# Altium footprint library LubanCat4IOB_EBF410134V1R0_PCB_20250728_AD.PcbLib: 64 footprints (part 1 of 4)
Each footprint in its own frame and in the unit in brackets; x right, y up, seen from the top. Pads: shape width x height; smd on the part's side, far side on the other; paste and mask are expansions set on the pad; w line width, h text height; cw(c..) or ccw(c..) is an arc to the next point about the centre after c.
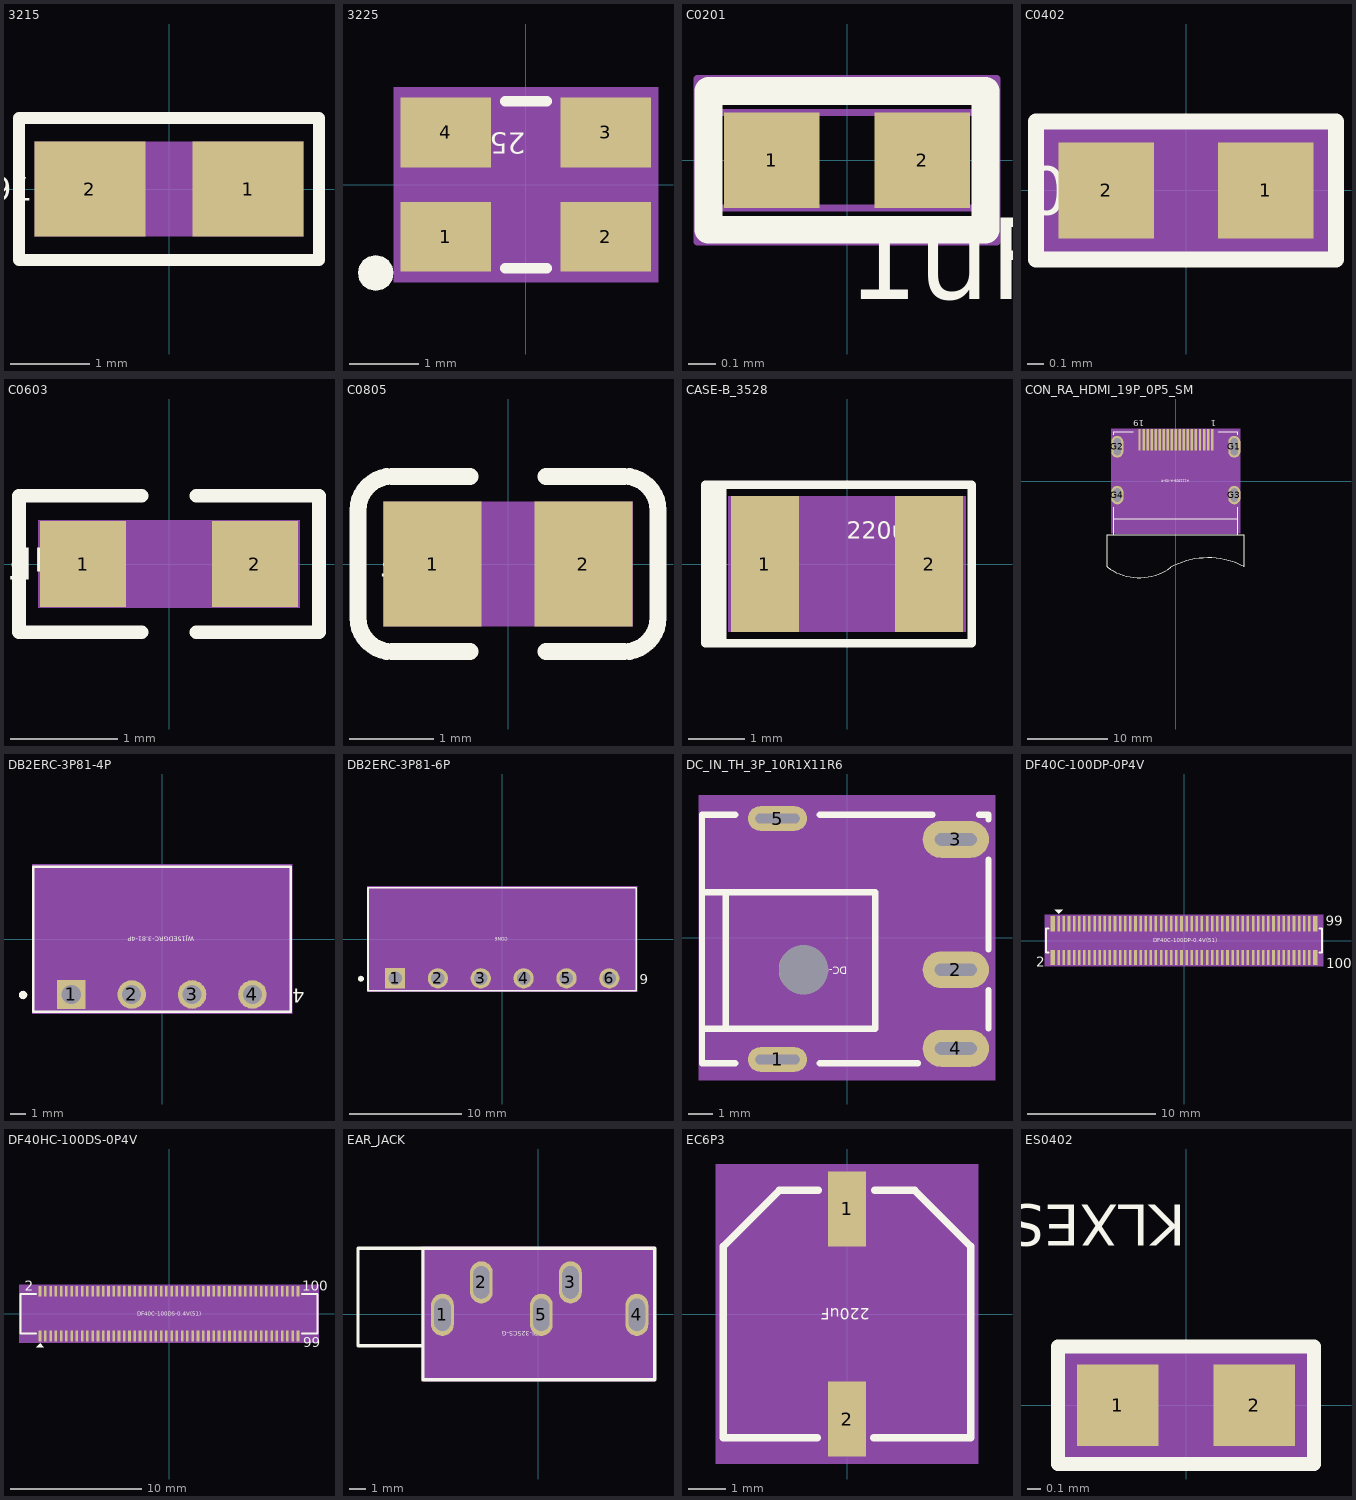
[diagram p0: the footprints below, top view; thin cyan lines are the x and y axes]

## 3215 [mm] "3215"
pads (2):
  rect 1.4x1.2 smd: 1(1.001,0) 2(-1.001,0)
Top Overlay:
  lines w0.15: -1.9,-0.899 1.9,-0.899 1.9,0.899 -1.9,0.899 -1.9,-0.899
  text "32.768KHz" at -1.08,0.15 h0.3
Top 3D Body:
  region: 1.699,0.599 1.699,-0.599 -1.699,-0.599 -1.699,0.599
Mechanical 17:
  text "1" at 0.848,0 h0.38
  text "2" at -1.153,0 h0.38
3D body: height 3.81, standoff 0, extent -1.699,-0.599 1.699,0.599

## 3225 [mm] "3225"
pads (4):
  rect 1.3x1 smd: 1(-1.15,-0.75) 2(1.15,-0.75) 3(1.15,0.75) 4(-1.15,0.75)
Top Overlay:
  dashed: -2.159,-1.525 -2.257,-1.505 -2.339,-1.45 -2.394,-1.368 -2.414,-1.27 -2.394,-1.172 -2.376,-1.145 -2.339,-1.09 -2.257,-1.035 -2.159,-1.015 -2.061,-1.035 -1.979,-1.09 -1.942,-1.145 -1.924,-1.172 -1.904,-1.27 -1.924,-1.368 -1.979,-1.45 -2.061,-1.505
  lines w0.15: -0.3,-1.2 0.3,-1.2 ; -0.3,1.2 0.3,1.2
  text "25MHz" at 0,0.75 h0.3
Top 3D Body:
  region: -1.9,1.4 -1.9,-1.4 1.9,-1.4 1.9,1.4
Mechanical 17:
  text "1" at -1.15,-0.384 h0.91
  text "3" at 1.15,1.116 h0.91
  text "4" at -1.15,1.116 h0.91
  text "2" at 1.15,-0.384 h0.91
Top Assembly:
  lines w0.15: -1.6,-1.25 1.6,-1.25 1.6,1.25 -1.6,1.25 -1.6,-1.25
3D body: height 3.81, standoff 0, extent -1.9,-1.4 1.9,1.4

## C0201 [mm] "C0201"
pads (2):
  rect 0.35x0.35 smd: 1(-0.275,0) 2(0.275,0)
Top Overlay:
  lines w0.102: -0.508,-0.254 0.508,-0.254 0.508,0.254 -0.508,0.254 -0.508,-0.254
  text ".Designator" at 0.762,-1.422 h0.76
  text "1uF" at 0,-0.51 h0.3
Top 3D Body:
  lines w0.025: -0.475,-0.175 -0.475,0.175 0.475,0.175 0.475,-0.175 -0.475,-0.175
Mechanical 17:
  text "1" at -0.275,-0.305 h0.76
  text "2" at 0.275,-0.305 h0.76
Top Assembly:
  lines w0.025: -0.55,-0.3 -0.55,0.3 0.55,0.3 0.55,-0.3 -0.55,-0.3 ; -0.475,-0.175 -0.475,0.175 0.475,0.175 0.475,-0.175 -0.475,-0.175
  text "1uF" at 0.762,-0.254 h0.76

## C0402 [mm] "C0402"
pads (2):
  rect 0.599x0.599 smd: 1(0.5,0) 2(-0.5,0)
Top Overlay:
  lines w0.102: -0.94,-0.432 0.94,-0.432 0.94,0.432 -0.94,0.432 -0.94,-0.432
  text "10uF" at -0.48,0.15 h0.3
Top 3D Body:
  region: -0.94,-0.432 -0.94,0.432 0.94,0.432 0.94,-0.432
Mechanical 17:
  text "1" at 0.246,0 h0.64
  text "2" at -0.754,0 h0.64
Top Assembly:
  dashed: 0.94,0.432 0.94,-0.432 -0.94,-0.432 -0.94,0.432
3D body: height 3.81, standoff 0, extent -0.94,-0.432 0.94,0.432

## C0603 [mil] "C0603"
pads (2):
  rect 31.5x31.5 smd: 1(-31.5,0) 2(31.5,0)
Top Overlay:
  lines w5: -10,-25 -55,-25 -55,25 -10,25 ; 10,-25 55,-25 55,25 10,25
  text "22uF" at -18.9,5.91 h11.81
Top 3D Body:
  region: -48,16 48,16 48,-16 -48,-16
Mechanical 17:
  text "2" at 13.5,0 h45
  text "1" at -49.5,0 h45
Top Assembly:
  text "C0603" at -117,37 h30
3D body: height 150, standoff 0, extent -48,-16 48,16

## C0805 [mm] "C0805"
pads (2):
  rect 1.16x1.47 smd: 1(-0.89,0) 2(0.89,0)
Top Overlay:
  lines w0.2: -0.45,-1.035 -1.37,-1.035 cw(c-1.37,-0.635) -1.77,-0.635 -1.77,0.635 cw(c-1.37,0.635) -1.37,1.035 -0.45,1.035 ; 0.45,-1.035 1.37,-1.035 ccw(c1.37,-0.635) 1.77,-0.635 1.77,0.635 ccw(c1.37,0.635) 1.37,1.035 0.45,1.035
  text "47uF" at -0.48,0.15 h0.3
Top 3D Body:
  region: -1.47,-0.735 -1.47,0.735 1.47,0.735 1.47,-0.735
Mechanical 17:
  text "2" at 0.575,0 h0.79
  text "1" at -1.205,0 h0.79
3D body: height 3.81, standoff 0, extent -1.47,-0.735 1.47,0.735

## CASE-B_3528 [mm] "CASE-B_3528"
pads (2):
  rect 1.2x2.4 smd: 1(-1.45,0) 2(1.45,0)
Top Overlay:
  lines w0.15: -2.2,1.4 -2.2,-1.4 ; -2.1,-1.4 -2.3,-1.4 -2.3,1.4 ; -2.4,-1.4 -2.4,1.4 ; -2.4,-1.4 -2.2,-1.4 ; -2.4,-1.4 -2.5,-1.4 -2.5,1.4 -2.4,1.4 ; -2.4,1.4 -2.3,1.4 ; -2.3,1.4 2.2,1.4 2.2,-1.4 -2.2,-1.4
  text "220uF" at 0,0.45 h0.3
Top 3D Body:
  region: -2.1,1.2 -2.1,-1.2 2.1,-1.2 2.1,1.2
Mechanical 17:
  text "1" at -1.45,0.254 h0.64
  text "2" at 1.45,0.254 h0.64
Top Assembly:
  lines w0.15: -1.72,-1.1 1.78,-1.1 1.78,1.1 -1.72,1.1 -1.72,-1.1
3D body: height 3.81, standoff 0, extent -2.1,-1.2 2.1,1.2

## CON_RA_HDMI_19P_0P5_SM [mil] "CON_RA_HDMI_19P_0P5_SM"
pads (23):
  rect 12x106 smd: 1(177.17,201.35) 2(157.48,201.35) 3(137.8,201.35) 4(118.11,201.35) 5(98.43,201.35) 6(78.74,201.35) 7(59.06,201.35) 8(39.37,201.35) 9(19.69,201.35) 10(0,201.35) 11(-19.69,201.35) 12(-39.37,201.35) 13(-59.06,201.35) 14(-78.74,201.35) 15(-98.43,201.35) 16(-118.11,201.35) 17(-137.8,201.35) 18(-157.48,201.35) 19(-177.17,201.35)
  oval 59x106 / inner round 60 / far side oval 59x106 hole 83 slot 35 at 0 deg: G1(285.43,167.89) G2(-285.43,167.89)
  oval 59x90 / inner round 60 / far side oval 59x90 hole 66 slot 35 at 0 deg: G3(285.43,-68.33) G4(-285.43,-68.33)
Top Overlay:
  lines w5.91: -303.26,-261.35 -303.26,-182.61 303.26,-182.61 303.26,-261.35 ; -334.65,-418.83 ccw(c-178.55,-211.88) -23.62,-419.71 cw(c156.34,-755.43) 334.65,-418.83 334.65,-261.35 -334.65,-261.35 -334.65,-418.83
  lines w6: -303.26,-128.37 -303.26,-261.35 303.26,-261.35 303.26,-128.37 ; -303.26,225.96 -303.26,240.83 -206.69,240.83 ; 206.69,240.83 303.26,240.83 303.26,225.96
  text "19" at -154.21,297.54 h30
  text "1" at 197.79,297.54 h30
  text "A111926-A-05-R" at 66.14,5.91 h11.81
Top Courtyard:
  dashed: -314.93,-254.35 314.93,-254.35 314.93,254.35 -314.93,254.35
Bottom Courtyard:
  drawing of 4 lines, arcs and shapes, not listed
Top 3D Body:
  region: -314.93,-254.35 314.93,-254.35 314.93,254.35 -314.93,254.35
Top Component Center:
  lines w1: -10,-10.26 10,-10.26 ; 0,-20.26 0,-0.26
Mechanical 17:
  text "18" at -141.74,201.35 h9.84
  text "10" at 15.74,201.35 h9.84
  text "16" at -102.37,201.35 h9.84
  text "15" at -82.69,201.35 h9.84
  text "13" at -43.31,201.35 h9.84
  text "12" at -23.63,201.35 h9.84
  text "9" at 27.56,201.35 h9.84
  text "7" at 66.93,201.35 h9.84
  text "6" at 86.61,201.35 h9.84
  text "4" at 125.98,201.35 h9.84
  text "3" at 145.67,201.35 h9.84
  text "1" at 185.04,201.35 h9.84
  text "19" at -161.43,201.35 h9.84
  text "14" at -63,201.35 h9.84
  text "G3" at 301.17,-68.33 h9.84
  text "G1" at 301.17,167.89 h9.84
  text "G4" at -269.69,-68.33 h9.84
  text "G2" at -269.69,167.89 h9.84
  text "5" at 106.3,201.35 h9.84
  text "2" at 165.35,201.35 h9.84
  text "8" at 47.24,201.35 h9.84
  text "11" at -3.94,201.35 h9.84
  text "17" at -122.06,201.35 h9.84
Top Assembly:
  lines w6: -296.26,-254.35 296.26,-254.35 296.26,233.83 -296.26,233.83 -296.26,-254.35
  text "1" at 169.54,281.35 h25
  text "19" at -199.02,277.07 h25
3D body: height 150, standoff 0, extent -314.93,-254.35 314.93,254.35

## DB2ERC-3P81-4P [mm] "DB2ERC-3P81-4P"
pads (4):
  rect 1.8x1.8 / inner round 1.524 / far side rect 1.8x1.8 hole 1.2: 1(-5.725,-3.5)
  round 1.8 / inner round 1.524 / far side round 1.8 hole 1.2: 2(-1.915,-3.5) 3(1.895,-3.5) 4(5.705,-3.5)
Top Overlay:
  dashed: -9.021,-3.53 -9.002,-3.628 -8.946,-3.71 -8.864,-3.765 -8.766,-3.785 -8.669,-3.765 -8.641,-3.747 -8.586,-3.71 -8.531,-3.628 -8.511,-3.53 -8.531,-3.432 -8.586,-3.35 -8.641,-3.313 -8.669,-3.294 -8.766,-3.275 -8.864,-3.294 -8.946,-3.35 -9.002,-3.432
  lines w0.15: -8.13,-4.6 8.11,-4.6 8.11,4.55 -8.13,4.55 -8.13,-4.6
  text "WJ15EDGRC-3.81-4P" at 2.04,0.15 h0.3
  text "4" at 9.014,-3.149 h0.89
Top 3D Body:
  region: -8.2,4.7 -8.2,-4.7 8.2,-4.7 8.2,4.7
Mechanical 17:
  text "3" at 2.149,-3.5 h0.64
  text "1" at -5.471,-3.5 h0.64
  text "2" at -1.661,-3.5 h0.64
  text "4" at 5.959,-3.5 h0.64
3D body: height 3.81, standoff 0, extent -8.2,-4.7 8.2,4.7

## DB2ERC-3P81-6P [mm] "DB2ERC-3P81-6P"
pads (6):
  rect 1.8x1.8 / inner round 1.524 / far side rect 1.8x1.8 hole 1.2: 1(-9.525,-3.5)
  round 1.8 hole 1.2: 2(-5.715,-3.5) 5(5.715,-3.5)
  round 1.8 / inner round 1.524 / far side round 1.8 hole 1.2: 3(-1.905,-3.5) 4(1.905,-3.5) 6(9.525,-3.5)
Top Overlay:
  dashed: -12.818,-3.53 -12.799,-3.628 -12.743,-3.71 -12.661,-3.766 -12.563,-3.785 -12.466,-3.766 -12.438,-3.747 -12.383,-3.71 -12.328,-3.628 -12.308,-3.53 -12.328,-3.432 -12.383,-3.35 -12.438,-3.313 -12.466,-3.294 -12.563,-3.275 -12.661,-3.294 -12.743,-3.35 -12.799,-3.432
  lines w0.15: -11.93,-4.6 11.93,-4.6 11.93,4.55 -11.93,4.55 -11.93,-4.6
  text "CON6" at 0.48,0.15 h0.3
  text "6" at 12.964,-3.149 h0.89
Top 3D Body:
  region: -12,4.7 -12,-4.7 12,-4.7 12,4.7
Mechanical 17:
  text "3" at -1.651,-3.5 h0.64
  text "6" at 9.779,-3.5 h0.64
  text "1" at -9.271,-3.5 h0.64
  text "4" at 2.159,-3.5 h0.64
  text "5" at 5.969,-3.5 h0.64
  text "2" at -5.461,-3.5 h0.64
3D body: height 3.81, standoff 0, extent -12,-4.7 12,4.7

## DC_IN_TH_3P_10R1X11R6 [mm] "DC_IN_TH_3P_10R1X11R6"
pads (6):
  oval 2.4x1.001 hole 1.801 slot 0.399 at 90 deg: 1(-2.826,-4.951) 5(-2.826,4.849)
  oval 2.7x1.5 hole 1.7 slot 0.5 at 90 deg: 2(4.426,-1.301) 3(4.426,3.998)
  oval 2.7x1.5 / inner round 1.524 / far side oval 2.7x1.5 hole 1.7 slot 0.5 at 90 deg: 4(4.426,-4.501)
  round 1.999 hole 1.999 unplated: ""(-1.774,-1.301)
Top Overlay:
  lines w0.254: -5.899,-3.701 1.149,-3.701 1.149,1.849 -5.65,1.849 -5.899,1.849 ; -4.926,-3.701 -4.926,1.849 ; -4.545,-5.1 -5.899,-5.1 -5.899,4.999 -4.545,4.999 ; -1.104,-5.1 2.887,-5.1 ; -1.104,4.999 3.479,4.999 ; 5.371,4.999 5.749,4.999 5.749,4.818 ; 5.749,-3.683 5.749,-2.121 ; 5.749,-0.483 5.749,3.18
  text "DC-044A-20A" at 0,-1.17 h0.3
Top 3D Body:
  region: -6.026,-5.801 6.026,-5.801 6.026,5.801 -6.026,5.801
Mechanical 17:
  text "4" at 4.426,-4.755 h0.64
  text "1" at -2.826,-5.205 h0.64
  text "5" at -2.826,4.595 h0.64
  text "2" at 4.426,-1.555 h0.64
  text "3" at 4.426,3.744 h0.64
Mechanical 19:
  dashed: -5.899,-3.602 1.05,-3.602 1.05,1.75 -5.899,1.75 -5.899,1.999 1.299,1.999 1.299,-3.851 -5.899,-3.851
3D body: height 3.81, standoff 0, extent -6.026,-5.801 6.026,5.801

## DF40C-100DP-0P4V [mm] "DF40C-100DP-0P4V"
pads (104):
  rect 0.2x1.2 smd: 1(-9.8,1.325) 2(-9.8,-1.325) 3(-9.4,1.325) 4(-9.4,-1.325) 5(-9,1.325) 6(-9,-1.325) 7(-8.6,1.325) 8(-8.6,-1.325) 9(-8.2,1.325) 10(-8.2,-1.325) 11(-7.8,1.325) 12(-7.8,-1.325) 13(-7.4,1.325) 14(-7.4,-1.325) 15(-7,1.325) 16(-7,-1.325) 17(-6.6,1.325) 18(-6.6,-1.325) 19(-6.2,1.325) 20(-6.2,-1.325) 21(-5.8,1.325) 22(-5.8,-1.325) 23(-5.4,1.325) 24(-5.4,-1.325) 25(-5,1.325) 26(-5,-1.325) 27(-4.6,1.325) 28(-4.6,-1.325) 29(-4.2,1.325) 30(-4.2,-1.325) 31(-3.8,1.325) 32(-3.8,-1.325) 33(-3.4,1.325) 34(-3.4,-1.325) 35(-3,1.325) 36(-3,-1.325) 37(-2.6,1.325) 38(-2.6,-1.325) 39(-2.2,1.325) 40(-2.2,-1.325) 41(-1.8,1.325) 42(-1.8,-1.325) 43(-1.4,1.325) 44(-1.4,-1.325) 45(-1,1.325) 46(-1,-1.325) 47(-0.6,1.325) 48(-0.6,-1.325) 49(-0.2,1.325) 50(-0.2,-1.325) 51(0.2,1.325) 52(0.2,-1.325) 53(0.6,1.325) 54(0.6,-1.325) 55(1,1.325) 56(1,-1.325) 57(1.4,1.325) 58(1.4,-1.325) 59(1.8,1.325) 60(1.8,-1.325) 61(2.2,1.325) 62(2.2,-1.325) 63(2.6,1.325) 64(2.6,-1.325) 65(3,1.325) 66(3,-1.325) 67(3.4,1.325) 68(3.4,-1.325) 69(3.8,1.325) 70(3.8,-1.325) 71(4.2,1.325) 72(4.2,-1.325) 73(4.6,1.325) 74(4.6,-1.325) 75(5,1.325) 76(5,-1.325) 77(5.4,1.325) 78(5.4,-1.325) 79(5.8,1.325) 80(5.8,-1.325) 81(6.2,1.325) 82(6.2,-1.325) 83(6.6,1.325) 84(6.6,-1.325) 85(7,1.325) 86(7,-1.325) 87(7.4,1.325) 88(7.4,-1.325) 89(7.8,1.325) 90(7.8,-1.325) 91(8.2,1.325) 92(8.2,-1.325) 93(8.6,1.325) 94(8.6,-1.325) 95(9,1.325) 96(9,-1.325) 97(9.4,1.325) 98(9.4,-1.325) 99(9.8,1.325) 100(9.8,-1.325)
  rect 0.35x1.2 smd: 101(-10.275,1.325) 102(-10.275,-1.325) 103(10.275,1.325) 104(10.275,-1.325)
Top Overlay:
  dashed: -10.1,2.4 -9.5,2.4 -9.8,2.1
  lines w0.15: -10.6,-0.925 -10.8,-0.925 -10.8,0.925 -10.6,0.925 ; 10.6,-0.925 10.8,-0.925 10.8,0.925 10.6,0.925
  text "DF40C-100DP-0.4V(51)" at -2.4,-0.15 h0.3
  text "99" at 11.075,1.142 h0.76
  text "100" at 11.126,-2.16 h0.76
  text "2" at -11.582,-2.033 h0.76
Top 3D Body:
  region: -10.9,2 -10.9,-2 10.9,-2 10.9,2
Mechanical 17:
  text "13" at -7.523,1.342 h0.3
  text "15" at -7.123,1.342 h0.3
  text "20" at -6.34,-1.325 h0.3
  text "22" at -5.94,-1.325 h0.3
  text "24" at -5.54,-1.325 h0.3
  text "26" at -5.14,-1.325 h0.3
  text "29" at -4.322,1.342 h0.3
  text "3" at -9.403,1.342 h0.3
  text "30" at -4.34,-1.325 h0.3
  text "31" at -3.922,1.342 h0.3
  text "32" at -3.94,-1.325 h0.3
  text "35" at -3.122,1.342 h0.3
  text "36" at -3.14,-1.325 h0.3
  text "37" at -2.722,1.342 h0.3
  text "38" at -2.74,-1.325 h0.3
  text "39" at -2.322,1.342 h0.3
  text "40" at -2.34,-1.325 h0.3
  text "41" at -1.922,1.342 h0.3
  text "42" at -1.94,-1.325 h0.3
  text "43" at -1.522,1.342 h0.3
  text "45" at -1.122,1.342 h0.3
  text "47" at -0.722,1.342 h0.3
  text "49" at -0.322,1.342 h0.3
  text "5" at -9.003,1.342 h0.3
  text "53" at 0.477,1.342 h0.3
  text "55" at 0.877,1.342 h0.3
  text "7" at -8.603,1.342 h0.3
  text "9" at -8.203,1.342 h0.3
  text "72" at 4.06,-1.325 h0.3
  text "86" at 6.86,-1.325 h0.3
  text "84" at 6.46,-1.325 h0.3
  text "48" at -0.74,-1.325 h0.3
  text "50" at -0.34,-1.325 h0.3
  text "64" at 2.46,-1.325 h0.3
  text "71" at 4.077,1.342 h0.3
  text "60" at 1.66,-1.325 h0.3
  text "69" at 3.677,1.342 h0.3
  text "63" at 2.477,1.342 h0.3
  text "61" at 2.077,1.342 h0.3
  text "59" at 1.677,1.342 h0.3
  text "90" at 7.66,-1.325 h0.3
  text "88" at 7.26,-1.325 h0.3
  text "62" at 2.06,-1.325 h0.3
  text "66" at 2.86,-1.325 h0.3
  text "25" at -5.122,1.342 h0.3
  text "67" at 3.277,1.342 h0.3
  text "46" at -1.14,-1.325 h0.3
  text "65" at 2.877,1.342 h0.3
  text "70" at 3.66,-1.325 h0.3
  text "21" at -5.922,1.342 h0.3
  text "74" at 4.46,-1.325 h0.3
  text "68" at 3.26,-1.325 h0.3
  text "23" at -5.522,1.342 h0.3
  text "19" at -6.323,1.342 h0.3
  text "54" at 0.46,-1.325 h0.3
  text "56" at 0.86,-1.325 h0.3
  text "98" at 9.26,-1.325 h0.3
  text "96" at 8.86,-1.325 h0.3
  text "94" at 8.46,-1.325 h0.3
  text "92" at 8.06,-1.325 h0.3
  text "85" at 6.878,1.342 h0.3
  text "83" at 6.478,1.342 h0.3
  text "6" at -9.02,-1.325 h0.3
  text "4" at -9.42,-1.325 h0.3
  text "10" at -8.34,-1.325 h0.3
  text "8" at -8.62,-1.325 h0.3
  text "16" at -7.14,-1.325 h0.3
  text "14" at -7.54,-1.325 h0.3
  text "78" at 5.26,-1.325 h0.3
  text "80" at 5.66,-1.325 h0.3
  text "89" at 7.678,1.342 h0.3
  text "87" at 7.278,1.342 h0.3
  text "77" at 5.277,1.342 h0.3
  text "75" at 4.877,1.342 h0.3
  text "81" at 6.077,1.342 h0.3
  text "95" at 8.878,1.342 h0.3
  text "93" at 8.478,1.342 h0.3
  text "99" at 9.678,1.342 h0.3
  text "97" at 9.278,1.342 h0.3
  text "82" at 6.06,-1.325 h0.3
  text "100" at 9.54,-1.325 h0.3
  text "104" at 10.015,-1.325 h0.3
  text "1" at -9.803,1.342 h0.3
  text "2" at -9.82,-1.325 h0.3
  text "58" at 1.26,-1.325 h0.3
  text "79" at 5.677,1.342 h0.3
  text "52" at 0.06,-1.325 h0.3
  text "101" at -10.535,1.325 h0.3
  text "102" at -10.535,-1.325 h0.3
  text "11" at -7.923,1.342 h0.3
  text "17" at -6.723,1.342 h0.3
  text "12" at -7.94,-1.325 h0.3
  text "18" at -6.74,-1.325 h0.3
  text "28" at -4.74,-1.325 h0.3
  text "34" at -3.54,-1.325 h0.3
  text "27" at -4.722,1.342 h0.3
  text "33" at -3.522,1.342 h0.3
  text "44" at -1.54,-1.325 h0.3
  text "51" at 0.078,1.342 h0.3
  text "57" at 1.277,1.342 h0.3
  text "76" at 4.86,-1.325 h0.3
  text "73" at 4.477,1.342 h0.3
  text "91" at 8.078,1.342 h0.3
  text "103" at 10.015,1.325 h0.3
Top Assembly:
  lines w0.15: -10.8,-1.5 -10.8,1.5 0,1.5 10.8,1.5 10.8,-1.5 -10.8,-1.5
3D body: height 3.81, standoff 0, extent -10.9,-2 10.9,2

## DF40HC-100DS-0P4V [mm] "DF40HC-100DS-0P4V"
pads (100):
  rect 0.2x0.8 smd: 1(-9.8,-1.7) 2(-9.8,1.7) 3(-9.4,-1.7) 4(-9.4,1.7) 5(-9,-1.7) 6(-9,1.7) 7(-8.6,-1.7) 8(-8.6,1.7) 9(-8.2,-1.7) 10(-8.2,1.7) 11(-7.8,-1.7) 12(-7.8,1.7) 13(-7.4,-1.7) 14(-7.4,1.7) 15(-7,-1.7) 16(-7,1.7) 17(-6.6,-1.7) 18(-6.6,1.7) 19(-6.2,-1.7) 20(-6.2,1.7) 21(-5.8,-1.7) 22(-5.8,1.7) 23(-5.4,-1.7) 24(-5.4,1.7) 25(-5,-1.7) 26(-5,1.7) 27(-4.6,-1.7) 28(-4.6,1.7) 29(-4.2,-1.7) 30(-4.2,1.7) 31(-3.8,-1.7) 32(-3.8,1.7) 33(-3.4,-1.7) 34(-3.4,1.7) 35(-3,-1.7) 36(-3,1.7) 37(-2.6,-1.7) 38(-2.6,1.7) 39(-2.2,-1.7) 40(-2.2,1.7) 41(-1.8,-1.7) 42(-1.8,1.7) 43(-1.4,-1.7) 44(-1.4,1.7) 45(-1,-1.7) 46(-1,1.7) 47(-0.6,-1.7) 48(-0.6,1.7) 49(-0.2,-1.7) 50(-0.2,1.7) 51(0.2,-1.7) 52(0.2,1.7) 53(0.6,-1.7) 54(0.6,1.7) 55(1,-1.7) 56(1,1.7) 57(1.4,-1.7) 58(1.4,1.7) 59(1.8,-1.7) 60(1.8,1.7) 61(2.2,-1.7) 62(2.2,1.7) 63(2.6,-1.7) 64(2.6,1.7) 65(3,-1.7) 66(3,1.7) 67(3.4,-1.7) 68(3.4,1.7) 69(3.8,-1.7) 70(3.8,1.7) 71(4.2,-1.7) 72(4.2,1.7) 73(4.6,-1.7) 74(4.6,1.7) 75(5,-1.7) 76(5,1.7) 77(5.4,-1.7) 78(5.4,1.7) 79(5.8,-1.7) 80(5.8,1.7) 81(6.2,-1.7) 82(6.2,1.7) 83(6.6,-1.7) 84(6.6,1.7) 85(7,-1.7) 86(7,1.7) 87(7.4,-1.7) 88(7.4,1.7) 89(7.8,-1.7) 90(7.8,1.7) 91(8.2,-1.7) 92(8.2,1.7) 93(8.6,-1.7) 94(8.6,1.7) 95(9,-1.7) 96(9,1.7) 97(9.4,-1.7) 98(9.4,1.7) 99(9.8,-1.7) 100(9.8,1.7)
Top Overlay:
  dashed: -10.1,-2.55 -9.5,-2.55 -9.8,-2.25
  lines w0.15: -10.1,-1.5 -11.3,-1.5 -11.3,1.5 -10.1,1.5 ; 10.1,-1.5 11.3,-1.5 11.3,1.5 10.1,1.5
  text "DF40C-100DS-0.4V(51)" at -2.4,-0.15 h0.3
  text "2" at -10.947,1.751 h0.76
  text "100" at 10.11,1.751 h0.76
  text "99" at 10.186,-2.567 h0.76
Top 3D Body:
  region: -11.4,2.2 -11.4,-2.2 11.4,-2.2 11.4,2.2
Mechanical 17:
  text "95" at 8.878,-1.682 h0.3
  text "93" at 8.478,-1.682 h0.3
  text "66" at 2.877,1.717 h0.3
  text "48" at -0.722,1.717 h0.3
  text "58" at 1.277,1.717 h0.3
  text "76" at 4.877,1.717 h0.3
  text "89" at 7.678,-1.682 h0.3
  text "94" at 8.478,1.717 h0.3
  text "56" at 0.877,1.717 h0.3
  text "60" at 1.677,1.717 h0.3
  text "70" at 3.677,1.717 h0.3
  text "44" at -1.522,1.717 h0.3
  text "46" at -1.122,1.717 h0.3
  text "87" at 7.278,-1.682 h0.3
  text "85" at 6.878,-1.682 h0.3
  text "54" at 0.477,1.717 h0.3
  text "72" at 4.077,1.717 h0.3
  text "52" at 0.078,1.717 h0.3
  text "42" at -1.922,1.717 h0.3
  text "50" at -0.322,1.717 h0.3
  text "74" at 4.477,1.717 h0.3
  text "62" at 2.077,1.717 h0.3
  text "64" at 2.477,1.717 h0.3
  text "92" at 8.078,1.717 h0.3
  text "47" at -0.722,-1.682 h0.3
  text "45" at -1.122,-1.682 h0.3
  text "41" at -1.922,-1.682 h0.3
  text "39" at -2.322,-1.682 h0.3
  text "81" at 6.077,-1.682 h0.3
  text "29" at -4.322,-1.682 h0.3
  text "27" at -4.722,-1.682 h0.3
  text "33" at -3.522,-1.682 h0.3
  text "31" at -3.922,-1.682 h0.3
  text "37" at -2.722,-1.682 h0.3
  text "35" at -3.122,-1.682 h0.3
  text "71" at 4.077,-1.682 h0.3
  text "73" at 4.477,-1.682 h0.3
  text "69" at 3.677,-1.682 h0.3
  text "75" at 4.877,-1.682 h0.3
  text "80" at 5.677,1.717 h0.3
  text "82" at 6.077,1.717 h0.3
  text "79" at 5.677,-1.682 h0.3
  text "77" at 5.277,-1.682 h0.3
  text "88" at 7.278,1.717 h0.3
  text "86" at 6.878,1.717 h0.3
  text "100" at 9.558,1.717 h0.3
  text "96" at 8.878,1.717 h0.3
  text "98" at 9.278,1.717 h0.3
  text "97" at 9.278,-1.682 h0.3
  text "83" at 6.478,-1.682 h0.3
  text "78" at 5.277,1.717 h0.3
  text "84" at 6.478,1.717 h0.3
  text "67" at 3.277,-1.682 h0.3
  text "30" at -4.322,1.717 h0.3
  text "40" at -2.322,1.717 h0.3
  text "43" at -1.522,-1.682 h0.3
  text "8" at -8.603,1.717 h0.3
  text "14" at -7.523,1.717 h0.3
  text "2" at -9.803,1.717 h0.3
  text "1" at -9.803,-1.682 h0.3
  text "20" at -6.323,1.717 h0.3
  text "19" at -6.323,-1.682 h0.3
  text "25" at -5.122,-1.682 h0.3
  text "49" at -0.322,-1.682 h0.3
  text "90" at 7.678,1.717 h0.3
  text "99" at 9.678,-1.682 h0.3
  text "68" at 3.277,1.717 h0.3
  text "91" at 8.078,-1.682 h0.3
  text "9" at -8.203,-1.682 h0.3
  text "7" at -8.603,-1.682 h0.3
  text "65" at 2.877,-1.682 h0.3
  text "63" at 2.477,-1.682 h0.3
  text "61" at 2.077,-1.682 h0.3
  text "6" at -9.003,1.717 h0.3
  text "59" at 1.677,-1.682 h0.3
  text "57" at 1.277,-1.682 h0.3
  text "55" at 0.877,-1.682 h0.3
  text "53" at 0.477,-1.682 h0.3
  text "51" at 0.078,-1.682 h0.3
  text "5" at -9.003,-1.682 h0.3
  text "4" at -9.403,1.717 h0.3
  text "38" at -2.722,1.717 h0.3
  text "36" at -3.122,1.717 h0.3
  text "34" at -3.522,1.717 h0.3
  text "32" at -3.922,1.717 h0.3
  text "3" at -9.403,-1.682 h0.3
  text "28" at -4.722,1.717 h0.3
  text "26" at -5.122,1.717 h0.3
  text "24" at -5.522,1.717 h0.3
  text "23" at -5.522,-1.682 h0.3
  text "22" at -5.922,1.717 h0.3
  text "21" at -5.922,-1.682 h0.3
  text "18" at -6.723,1.717 h0.3
  text "17" at -6.723,-1.682 h0.3
  text "16" at -7.123,1.717 h0.3
  text "15" at -7.123,-1.682 h0.3
  text "13" at -7.523,-1.682 h0.3
  text "12" at -7.923,1.717 h0.3
  text "11" at -7.923,-1.682 h0.3
  text "10" at -8.323,1.717 h0.3
Top Assembly:
  lines w0.15: -11.3,-1.7 11.3,-1.7 11.3,1.7 0,1.7 -11.3,1.7 -11.3,-1.7
3D body: height 3.81, standoff 0, extent -11.4,-2.2 11.4,2.2

## EAR_JACK [mm] "EAR_JACK"
pads (5):
  oval 1.4x2.6 / inner round 1.524 / far side oval 1.4x2.6 hole 1 slot 2 at 90 deg: 1(-5.904,-0.05) 2(-3.504,1.95) 3(1.996,1.95) 4(6.096,-0.05) 5(0.196,-0.05)
Top Overlay:
  lines w0.2: -7.18,-1.956 -11.117,-1.956 -11.117,4.064 -7.18,4.064 7.196,4.064 7.196,-4.064 -7.104,-4.064 -7.104,4.064
  text "PJ-325C5-G" at 0,-1.05 h0.3
Top 3D Body:
  region: -7.2,-4.15 7.2,-4.15 7.2,4.15 -7.2,4.15
Mechanical 17:
  text "2" at -3.504,1.696 h0.64
  text "3" at 1.996,1.696 h0.64
  text "5" at 0.196,-0.304 h0.64
  text "4" at 6.096,-0.304 h0.64
  text "1" at -5.904,-0.304 h0.64
Top Assembly:
  dashed: -7.2,4.15 -7.2,-4.15 7.2,-4.15 7.2,4.15
3D body: height 3.81, standoff 0, extent -7.2,-4.15 7.2,4.15

## EC6P3 [mm] "EC6P3"
pads (2):
  rect 1.001x1.999 smd: 1(0,2.8) 2(0,-2.8)
Top Overlay:
  lines w0.2: -0.787,-3.3 -3.3,-3.3 -3.3,1.8 -1.8,3.3 -0.762,3.3 ; 0.711,-3.3 3.3,-3.3 3.3,1.8 1.8,3.3 0.737,3.3
  text "220uF" at 0.6,0.15 h0.3
Top 3D Body:
  region: -3.5,4 -3.5,-4 3.5,-4 3.5,4
Mechanical 17:
  text "1" at 0.356,2.8 h0.89
  text "2" at 0.356,-2.8 h0.89
3D body: height 3.81, standoff 0, extent -3.5,-4 3.5,4

## ES0402 [mm] "ES0402"
pads (2):
  rect 0.599x0.599 smd: 1(-0.5,0) 2(0.5,0)
Top Overlay:
  lines w0.102: -0.94,-0.432 0.94,-0.432 0.94,0.432 -0.94,0.432 -0.94,-0.432
  text "KLXES15AAA1" at 0,1.47 h0.3
Top 3D Body:
  region: 0.94,0.432 0.94,-0.432 -0.94,-0.432 -0.94,0.432
Mechanical 17:
  text "2" at 0.5,0.254 h0.64
  text "1" at -0.5,0.254 h0.64
Top Assembly:
  dashed: -0.94,-0.432 -0.94,0.432 0.94,0.432 0.94,-0.432
3D body: height 3.81, standoff 0, extent -0.94,-0.432 0.94,0.432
